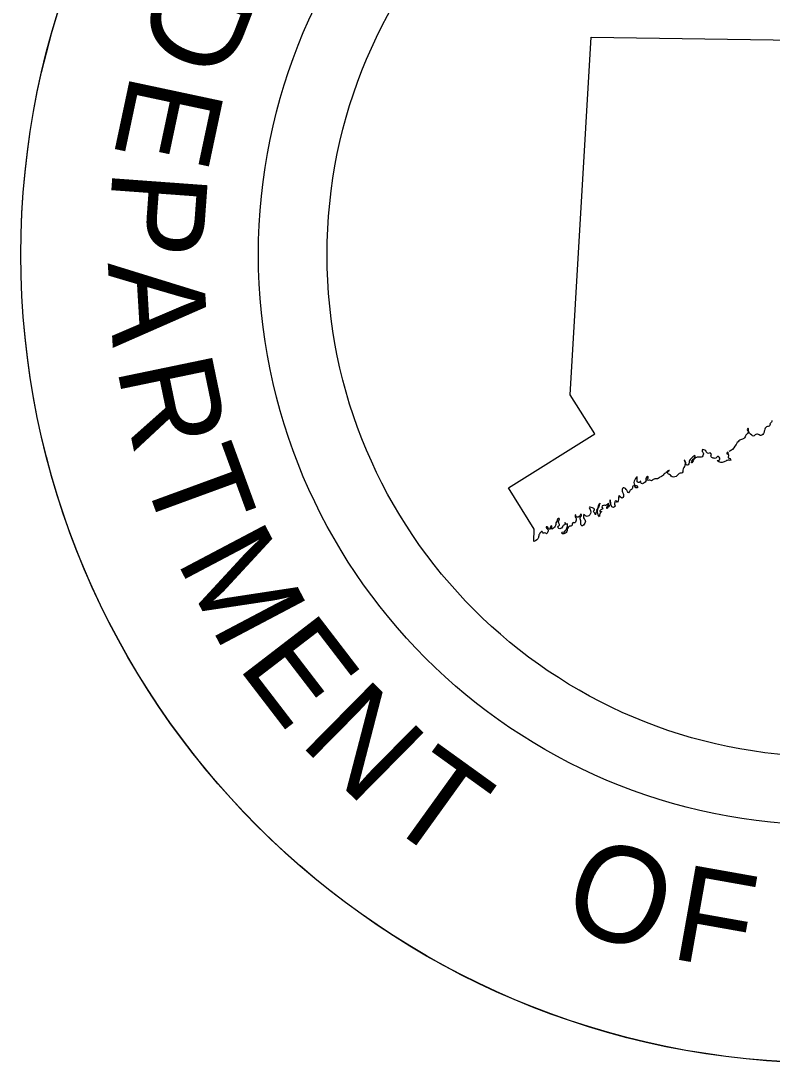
# Model space of a CAD drawing. Extents: x 0 to 1270, y 0 to 830.
# Drawn here: x 616.69 to 629.27, y 29.83 to 47.27 of the extents above; entities that cross this region are included whole.
import ezdxf

# ---------------------------------------------------------------- set-up
doc = ezdxf.new("R2010")
doc.units = 0
doc.layers.add('CT_Graphics', color=7, linetype='Continuous')

msp = doc.modelspace()

# ---------------------------------------------------------------- linework, layer by layer
at = {"layer": 'CT_Graphics'}
for p, q in [((625.89, 41.013), (626.24, 47)), ((625.89, 41.013), (626.24, 47)), ((626.24, 47), (630.173, 46.938)), ((626.24, 47), (630.173, 46.938)), ((626.301, 40.363), (625.89, 41.013)), ((626.301, 40.363), (625.89, 41.013)), ((624.855, 39.458), (626.301, 40.363)), ((624.855, 39.458), (626.301, 40.363)), ((625.289, 38.765), (624.855, 39.458)), ((625.289, 38.765), (624.855, 39.458))]:
    msp.add_line(p, q, dxfattribs=at)
msp.add_lwpolyline([(625.283, 38.561), (625.289, 38.765)], dxfattribs=at)
msp.add_lwpolyline([(625.283, 38.561), (625.289, 38.765)], dxfattribs=at)
for centre, major_axis in [((630.218, 43.361), (0, 13.525)), ((630.219, 43.358), (0, 13.525)), ((630.218, 43.361), (0, 9.547)), ((630.219, 43.358), (0, 8.399))]:
    msp.add_ellipse(centre, major_axis=major_axis, ratio=0.99999, dxfattribs=at)
for points in [[(629.265, 40.584), (629.259, 40.556), (629.235, 40.527), (629.235, 40.5), (629.206, 40.484), (629.179, 40.478), (629.143, 40.42), (629.125, 40.366), (629.098, 40.341), (629.069, 40.336), (629.041, 40.353), (628.986, 40.344), (628.958, 40.323), (628.929, 40.339), (628.875, 40.424), (628.869, 40.454), (628.853, 40.427), (628.873, 40.4), (628.859, 40.369), (628.833, 40.342), (628.798, 40.285), (628.743, 40.263), (628.714, 40.244), (628.687, 40.215), (628.606, 40.1), (628.548, 40.065)], [(629.265, 40.584), (629.259, 40.556), (629.235, 40.527), (629.235, 40.5), (629.206, 40.484), (629.179, 40.478), (629.143, 40.42), (629.125, 40.366), (629.098, 40.341), (629.069, 40.336), (629.041, 40.353), (628.986, 40.344), (628.958, 40.323), (628.929, 40.339), (628.875, 40.424), (628.869, 40.454), (628.853, 40.427), (628.873, 40.4), (628.859, 40.369), (628.833, 40.342), (628.798, 40.285), (628.743, 40.263), (628.714, 40.244), (628.687, 40.215), (628.606, 40.1), (628.548, 40.065)], [(628.513, 40.062), (628.537, 40.035), (628.505, 40.032), (628.534, 40.021), (628.537, 39.962), (628.566, 39.947), (628.577, 39.919), (628.55, 39.919), (628.494, 39.907), (628.437, 39.884), (628.381, 39.895), (628.352, 39.914), (628.381, 39.914), (628.394, 39.941), (628.386, 39.97), (628.357, 39.981), (628.329, 39.955), (628.303, 39.952), (628.246, 39.99), (628.254, 40.017), (628.231, 40.044), (628.204, 40.033), (628.176, 40.049), (628.16, 40.076), (628.128, 40.094), (628.101, 40.095), (628.101, 40.068), (628.118, 40.041), (628.117, 40.011), (628.099, 39.978), (628.018, 39.97), (627.961, 39.933), (627.922, 39.876), (627.926, 39.907), (627.951, 39.936), (627.975, 39.965), (627.981, 39.995), (627.926, 39.96), (627.883, 39.901), (627.881, 39.874), (627.863, 39.845), (627.835, 39.839), (627.822, 39.895), (627.797, 39.922), (627.812, 39.895), (627.814, 39.868), (627.811, 39.839), (627.777, 39.753), (627.774, 39.723), (627.746, 39.705), (627.717, 39.697), (627.663, 39.649), (627.578, 39.654), (627.554, 39.683), (627.524, 39.696), (627.524, 39.726), (627.553, 39.75), (627.526, 39.742), (627.499, 39.713), (627.47, 39.699), (627.421, 39.646), (627.392, 39.637), (627.365, 39.613), (627.309, 39.608), (627.28, 39.598), (627.253, 39.578), (627.223, 39.589), (627.196, 39.579)], [(628.513, 40.062), (628.537, 40.035), (628.505, 40.032), (628.534, 40.021), (628.537, 39.962), (628.566, 39.947), (628.577, 39.919), (628.55, 39.919), (628.494, 39.907), (628.437, 39.884), (628.381, 39.895), (628.352, 39.914), (628.381, 39.914), (628.394, 39.941), (628.386, 39.97), (628.357, 39.981), (628.329, 39.955), (628.303, 39.952), (628.246, 39.99), (628.254, 40.017), (628.231, 40.044), (628.204, 40.033), (628.176, 40.049), (628.16, 40.076), (628.128, 40.094), (628.101, 40.095), (628.101, 40.068), (628.118, 40.041), (628.117, 40.011), (628.099, 39.978), (628.018, 39.97), (627.961, 39.933), (627.922, 39.876), (627.926, 39.907), (627.951, 39.936), (627.975, 39.965), (627.981, 39.995), (627.926, 39.96), (627.883, 39.901), (627.881, 39.874), (627.863, 39.845), (627.835, 39.839), (627.822, 39.895), (627.797, 39.922), (627.812, 39.895), (627.814, 39.868), (627.811, 39.839), (627.777, 39.753), (627.774, 39.723), (627.746, 39.705), (627.717, 39.697), (627.663, 39.649), (627.578, 39.654), (627.554, 39.683), (627.524, 39.696), (627.524, 39.726), (627.553, 39.75), (627.526, 39.742), (627.499, 39.713), (627.47, 39.699), (627.421, 39.646), (627.392, 39.637), (627.365, 39.613), (627.309, 39.608), (627.28, 39.598), (627.253, 39.578), (627.223, 39.589), (627.196, 39.579)], [(627.199, 39.582), (627.171, 39.594), (627.194, 39.622), (627.186, 39.651), (627.161, 39.625), (627.156, 39.568), (627.128, 39.539), (627.099, 39.527), (627.07, 39.543), (627.07, 39.57), (627.043, 39.549), (627.014, 39.559), (627.014, 39.614), (627.01, 39.641), (626.984, 39.613), (626.96, 39.527), (626.979, 39.498), (627.008, 39.489), (627.018, 39.46), (626.989, 39.46), (626.965, 39.487), (626.938, 39.487), (626.936, 39.457), (626.884, 39.399), (626.874, 39.372), (626.847, 39.398), (626.803, 39.455), (626.776, 39.46), (626.76, 39.43), (626.769, 39.374), (626.782, 39.347), (626.763, 39.288), (626.733, 39.301), (626.709, 39.326), (626.694, 39.243), (626.68, 39.215), (626.659, 39.242), (626.635, 39.211), (626.632, 39.183), (626.642, 39.154), (626.616, 39.13), (626.588, 39.143), (626.559, 39.256), (626.562, 39.227), (626.556, 39.17), (626.53, 39.14), (626.503, 39.113), (626.506, 39.14), (626.53, 39.168), (626.53, 39.199), (626.503, 39.173), (626.474, 39.164), (626.446, 39.165), (626.42, 39.136), (626.435, 39.106), (626.404, 39.09), (626.387, 39.062), (626.414, 39.062), (626.392, 39.033), (626.384, 38.984)], [(627.199, 39.582), (627.171, 39.594), (627.194, 39.622), (627.186, 39.651), (627.161, 39.625), (627.156, 39.568), (627.128, 39.539), (627.099, 39.527), (627.07, 39.543), (627.07, 39.57), (627.043, 39.549), (627.014, 39.559), (627.014, 39.614), (627.01, 39.641), (626.984, 39.613), (626.96, 39.527), (626.979, 39.498), (627.008, 39.489), (627.018, 39.46), (626.989, 39.46), (626.965, 39.487), (626.938, 39.487), (626.936, 39.457), (626.884, 39.399), (626.874, 39.372), (626.847, 39.398), (626.803, 39.455), (626.776, 39.46), (626.76, 39.43), (626.769, 39.374), (626.782, 39.347), (626.763, 39.288), (626.733, 39.301), (626.709, 39.326), (626.694, 39.243), (626.68, 39.215), (626.659, 39.242), (626.635, 39.211), (626.632, 39.183), (626.642, 39.154), (626.616, 39.13), (626.588, 39.143), (626.559, 39.256), (626.562, 39.227), (626.556, 39.17), (626.53, 39.14), (626.503, 39.113), (626.506, 39.14), (626.53, 39.168), (626.53, 39.199), (626.503, 39.173), (626.474, 39.164), (626.446, 39.165), (626.42, 39.136), (626.435, 39.106), (626.404, 39.09), (626.387, 39.062), (626.414, 39.062), (626.392, 39.033), (626.384, 38.984)], [(626.382, 38.971), (626.349, 39.057), (626.385, 39.202), (626.353, 39.117), (626.333, 39.09), (626.334, 39.062), (626.318, 39.033), (626.315, 39.006), (626.302, 39.033), (626.28, 39.062), (626.298, 39.09), (626.24, 39.129), (626.212, 39.133), (626.232, 39.078), (626.201, 38.992), (626.145, 38.988), (626.116, 39.011), (626.115, 38.982), (626.115, 38.955), (626.137, 38.926), (626.145, 38.899), (626.138, 38.869), (626.083, 38.821), (626.071, 38.85), (626.068, 38.907), (626.059, 38.937), (626.057, 38.963), (626.078, 38.992), (626.071, 39.02), (626.052, 38.99), (626.025, 38.968), (625.997, 38.966), (625.982, 39.006)], [(626.382, 38.971), (626.349, 39.057), (626.385, 39.202), (626.353, 39.117), (626.333, 39.09), (626.334, 39.062), (626.318, 39.033), (626.315, 39.006), (626.302, 39.033), (626.28, 39.062), (626.298, 39.09), (626.24, 39.129), (626.212, 39.133), (626.232, 39.078), (626.201, 38.992), (626.145, 38.988), (626.116, 39.011), (626.115, 38.982), (626.115, 38.955), (626.137, 38.926), (626.145, 38.899), (626.138, 38.869), (626.083, 38.821), (626.071, 38.85), (626.068, 38.907), (626.059, 38.937), (626.057, 38.963), (626.078, 38.992), (626.071, 39.02), (626.052, 38.99), (626.025, 38.968), (625.997, 38.966), (625.982, 39.006)], [(625.982, 39.014), (625.973, 38.985), (625.992, 38.929), (625.985, 38.901), (625.968, 38.872), (625.939, 38.877), (625.914, 38.821), (625.884, 38.815), (625.842, 38.756), (625.836, 38.726), (625.809, 38.698), (625.782, 38.689), (625.756, 38.689), (625.755, 38.716), (625.783, 38.719), (625.812, 38.743), (625.831, 38.77), (625.841, 38.799), (625.839, 38.856), (625.813, 38.853), (625.801, 38.88), (625.804, 38.853), (625.775, 38.827), (625.756, 38.799), (625.7, 38.775), (625.684, 38.802), (625.71, 38.831), (625.694, 38.886), (625.707, 38.944), (625.68, 38.934), (625.67, 38.904), (625.648, 38.875), (625.649, 38.847), (625.611, 38.786), (625.584, 38.769), (625.578, 38.824), (625.555, 38.796), (625.554, 38.767), (625.525, 38.772), (625.516, 38.799), (625.489, 38.804), (625.5, 38.776), (625.522, 38.749), (625.514, 38.721), (625.493, 38.69), (625.465, 38.706), (625.436, 38.7), (625.422, 38.729), (625.395, 38.713), (625.364, 38.655), (625.358, 38.625), (625.283, 38.561)], [(625.982, 39.014), (625.973, 38.985), (625.992, 38.929), (625.985, 38.901), (625.968, 38.872), (625.939, 38.877), (625.914, 38.821), (625.884, 38.815), (625.842, 38.756), (625.836, 38.726), (625.809, 38.698), (625.782, 38.689), (625.756, 38.689), (625.755, 38.716), (625.783, 38.719), (625.812, 38.743), (625.831, 38.77), (625.841, 38.799), (625.839, 38.856), (625.813, 38.853), (625.801, 38.88), (625.804, 38.853), (625.775, 38.827), (625.756, 38.799), (625.7, 38.775), (625.684, 38.802), (625.71, 38.831), (625.694, 38.886), (625.707, 38.944), (625.68, 38.934), (625.67, 38.904), (625.648, 38.875), (625.649, 38.847), (625.611, 38.786), (625.584, 38.769), (625.578, 38.824), (625.555, 38.796), (625.554, 38.767), (625.525, 38.772), (625.516, 38.799), (625.489, 38.804), (625.5, 38.776), (625.522, 38.749), (625.514, 38.721), (625.493, 38.69), (625.465, 38.706), (625.436, 38.7), (625.422, 38.729), (625.395, 38.713), (625.364, 38.655), (625.358, 38.625), (625.283, 38.561)]]:
    msp.add_spline(points, degree=3, dxfattribs=at)

# ---------------------------------------------------------------- texts
for s, rotation, p in [('D', 248.9249, (619.175, 48.235)), ('E', 257.9978, (618.545, 46.432)), ('P', 265.8361, (618.235, 44.812)), ('A', 273.4128, (618.148, 43.219)), ('R', 281.7094, (618.295, 41.479)), ('T', 290.1103, (618.698, 39.757)), ('M', 297.8049, (619.284, 38.247)), ('E', 307.5238, (620.304, 36.475)), ('N', 315.3621, (621.336, 35.187)), ('T', 324.2342, (622.703, 33.915)), ('O', 340.6959, (625.687, 32.173)), ('F', 349.9172, (627.539, 31.591))]:
    msp.add_text(s, height=1.6, rotation=rotation, dxfattribs=at).set_placement(p)

doc.saveas('drawing.dxf')
